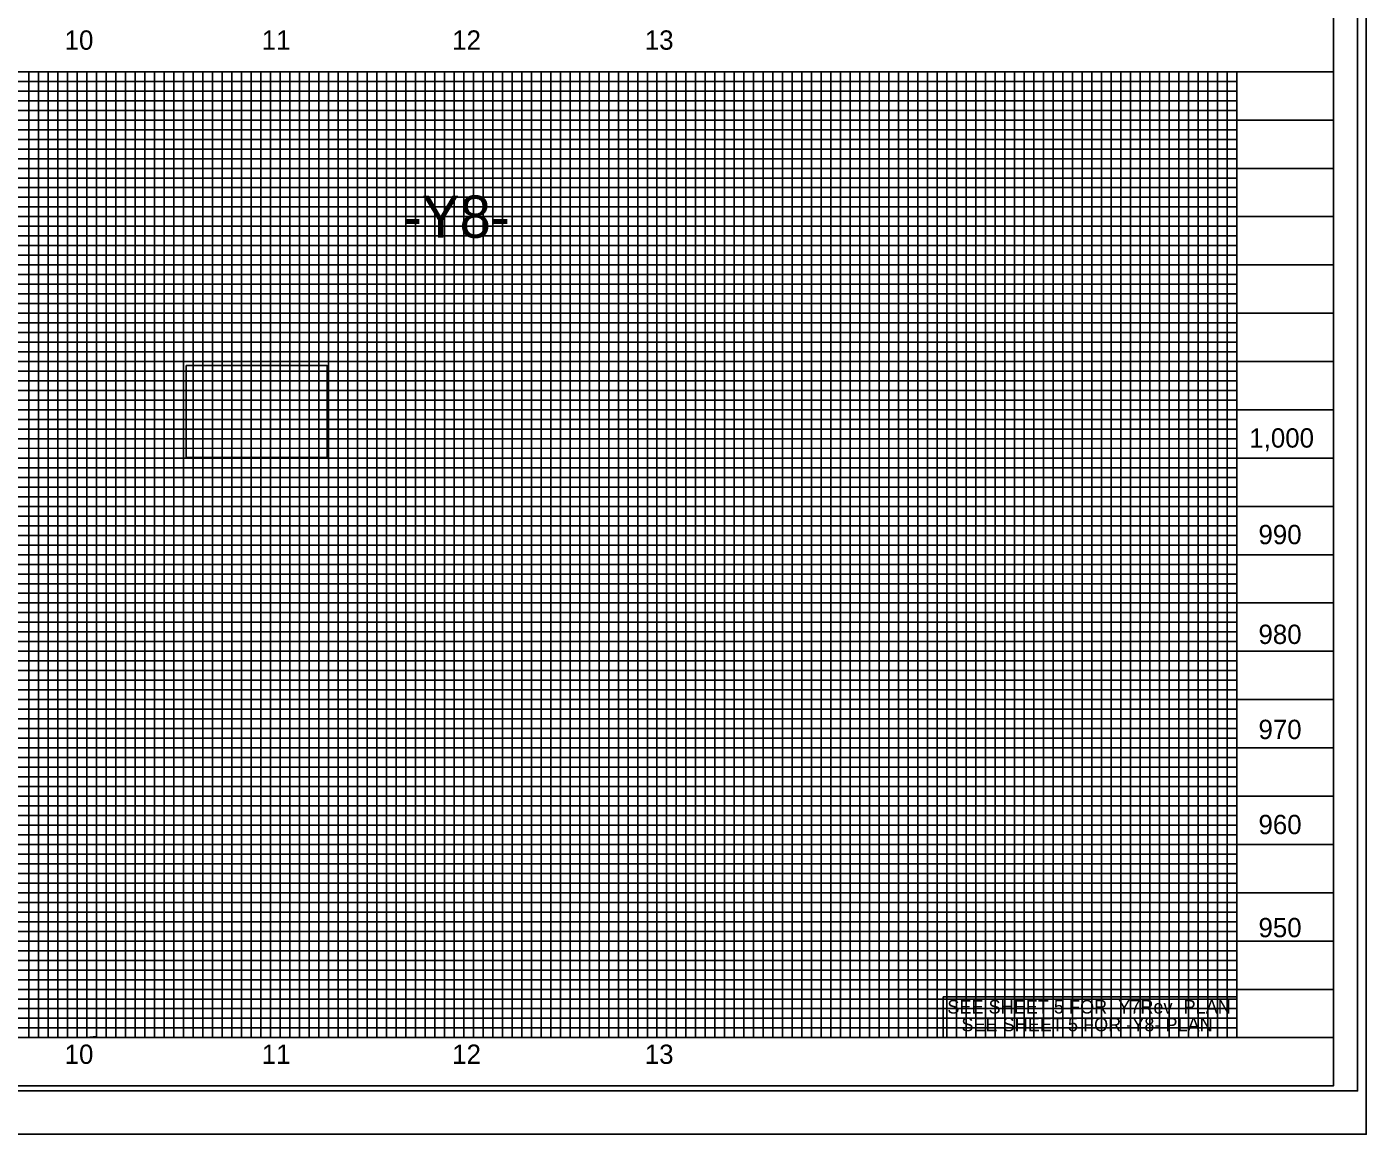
# Model space of a CAD drawing. Extents: x 1621288 to 1629363, y 896995 to 899414.
# Drawn here: x 1628293 to 1628986, y 896995 to 897568 of the extents above; entities that cross this region are included whole.
import ezdxf

# ---------------------------------------------------------------- set-up
doc = ezdxf.new("R2010")
doc.units = 0
for name, color, linetype in [('Exist Profile Cell', 7, 'Continuous'), ('Exist Structure Minor Pipes CMAP 112inx75in', 7, 'Continuous'), ('Exist Vertical Profile Horizontal Axis Label Major', 7, 'Continuous'), ('Exist XS Ground Line', 7, 'Continuous'), ('Prop Horizontal Alignment Curve and Spiral Data', 7, 'Continuous'), ('Prop Terminator CELL', 7, 'Continuous'), ('Prop Vertical Profile Curve Label', 7, 'Continuous'), ('Prop Vertical Profile Grade', 7, 'Continuous'), ('Prop VPI Label', 7, 'Continuous'), ('Sheet Layout Plan Border', 7, 'Continuous'), ('Sheet Layout Profile Border', 7, 'Continuous'), ('Sheet Layout Profile Border Port 2', 7, 'Continuous')]:
    doc.layers.add(name, color=color, linetype=linetype)

msp = doc.modelspace()

# ---------------------------------------------------------------- linework, layer by layer
at = {"layer": 'Exist Profile Cell'}
for p, q in [((1627519.38, 897539.66), (1628919.38, 897539.66)), ((1628919.38, 897534.66), (1627519.38, 897534.66)), ((1627519.38, 897529.66), (1628919.38, 897529.66)), ((1628919.38, 897524.66), (1627519.38, 897524.66)), ((1627519.38, 897514.66), (1628919.38, 897514.66)), ((1628919.38, 897509.66), (1627519.38, 897509.66)), ((1627519.38, 897504.66), (1628919.38, 897504.66)), ((1628919.38, 897499.66), (1627519.38, 897499.66)), ((1627519.38, 897489.66), (1628919.38, 897489.66)), ((1628919.38, 897484.66), (1627519.38, 897484.66)), ((1627519.38, 897479.66), (1628919.38, 897479.66)), ((1628919.38, 897474.66), (1627519.38, 897474.66)), ((1627519.38, 897464.66), (1628919.38, 897464.66)), ((1628919.38, 897459.66), (1627519.38, 897459.66)), ((1627519.38, 897454.66), (1628919.38, 897454.66)), ((1628919.38, 897449.66), (1627519.38, 897449.66)), ((1627519.38, 897439.66), (1628919.38, 897439.66)), ((1628919.38, 897434.66), (1627519.38, 897434.66)), ((1627519.38, 897429.66), (1628919.38, 897429.66)), ((1628919.38, 897424.66), (1627519.38, 897424.66)), ((1627519.38, 897414.66), (1628919.38, 897414.66)), ((1628919.38, 897409.66), (1627519.38, 897409.66)), ((1627519.38, 897404.66), (1628919.38, 897404.66)), ((1628919.38, 897399.66), (1627519.38, 897399.66)), ((1627519.38, 897389.66), (1628919.38, 897389.66)), ((1628919.38, 897384.66), (1627519.38, 897384.66)), ((1627519.38, 897379.66), (1628919.38, 897379.66)), ((1628919.38, 897374.66), (1627519.38, 897374.66)), ((1627519.38, 897364.66), (1628919.38, 897364.66)), ((1628919.38, 897359.66), (1627519.38, 897359.66)), ((1627519.38, 897354.66), (1628919.38, 897354.66)), ((1628919.38, 897349.66), (1627519.38, 897349.81)), ((1627519.38, 897339.66), (1628919.38, 897339.66)), ((1628919.38, 897334.66), (1627519.38, 897334.66)), ((1627519.38, 897329.66), (1628919.38, 897329.66)), ((1628919.38, 897324.66), (1627519.38, 897324.66)), ((1627519.38, 897314.66), (1628919.38, 897314.66)), ((1628919.38, 897309.66), (1627519.38, 897309.66)), ((1627519.38, 897304.66), (1628919.38, 897304.66)), ((1628919.38, 897299.66), (1627519.38, 897299.66)), ((1627519.38, 897289.66), (1628919.38, 897289.66)), ((1628919.38, 897284.66), (1627519.38, 897284.66)), ((1627519.38, 897279.66), (1628919.38, 897279.66)), ((1628919.38, 897274.66), (1627519.38, 897274.66)), ((1627519.38, 897264.66), (1628919.38, 897264.66)), ((1628919.38, 897259.66), (1627519.38, 897259.66)), ((1627519.38, 897254.66), (1628919.38, 897254.66)), ((1628919.38, 897249.66), (1627519.38, 897249.66)), ((1627519.38, 897239.66), (1628919.38, 897239.66)), ((1628919.38, 897234.66), (1627519.38, 897234.66)), ((1627519.38, 897229.66), (1628919.38, 897229.66)), ((1628919.38, 897224.66), (1627519.38, 897224.66)), ((1627519.38, 897214.66), (1628919.38, 897214.66)), ((1628919.38, 897209.66), (1627519.38, 897209.66)), ((1627519.38, 897204.66), (1628919.38, 897204.66)), ((1628919.38, 897199.66), (1627519.38, 897199.66)), ((1627519.38, 897189.66), (1628919.38, 897189.66)), ((1628919.38, 897184.66), (1627519.38, 897184.66)), ((1627519.38, 897179.66), (1628919.38, 897179.66)), ((1628919.38, 897174.66), (1627519.38, 897174.66)), ((1627519.38, 897164.66), (1628919.38, 897164.66)), ((1628919.38, 897159.66), (1627519.38, 897159.66)), ((1627519.38, 897154.66), (1628919.38, 897154.66)), ((1628919.38, 897149.66), (1627519.38, 897149.66)), ((1627519.38, 897139.66), (1628919.38, 897139.66)), ((1628919.38, 897134.66), (1627519.38, 897134.66)), ((1627519.38, 897129.66), (1628919.38, 897129.66)), ((1628919.38, 897124.66), (1627519.38, 897124.66)), ((1627519.38, 897114.66), (1628919.38, 897114.66)), ((1628919.38, 897109.66), (1627519.38, 897109.66)), ((1627519.38, 897104.66), (1628919.38, 897104.66)), ((1628919.38, 897099.66), (1627519.38, 897099.66)), ((1627519.38, 897089.66), (1628919.38, 897089.66)), ((1628919.38, 897084.66), (1627519.38, 897084.66)), ((1627519.38, 897079.66), (1628919.38, 897079.66)), ((1628919.38, 897074.66), (1627519.38, 897074.66)), ((1627519.38, 897064.66), (1628919.38, 897064.66)), ((1628919.38, 897059.66), (1627519.38, 897059.66)), ((1627519.38, 897054.66), (1628919.38, 897054.66)), ((1627519.38, 897049.66), (1628919.38, 897049.66)), ((1628919.38, 897049.66), (1628919.38, 897049.66))]:
    msp.add_line(p, q, dxfattribs=at)
for points in [[(1628289.38, 897544.66), (1628299.38, 897544.66), (1628299.38, 897044.66), (1628304.38, 897044.66), (1628304.38, 897544.66), (1628309.38, 897544.66), (1628309.38, 897044.66), (1628314.38, 897044.66), (1628314.38, 897544.66), (1628324.38, 897544.66), (1628324.38, 897044.66), (1628329.08, 897045.21), (1628329.38, 897044.66), (1628329.38, 897544.66), (1628334.38, 897544.66), (1628334.38, 897044.66), (1628339.38, 897044.66), (1628339.38, 897544.66), (1628349.38, 897544.66), (1628349.38, 897044.66), (1628354.38, 897044.66)], [(1628354.38, 897044.66), (1628354.38, 897544.66), (1628359.38, 897544.66), (1628359.38, 897044.66), (1628364.38, 897044.66), (1628364.38, 897544.66), (1628374.38, 897544.66), (1628374.38, 897044.66), (1628379.38, 897044.66), (1628379.38, 897544.66), (1628384.38, 897544.66), (1628384.38, 897044.66), (1628389.38, 897044.66), (1628389.38, 897544.66), (1628399.38, 897544.66), (1628399.38, 897044.66), (1628404.38, 897044.66), (1628404.38, 897544.66), (1628409.38, 897544.66), (1628409.38, 897044.66), (1628414.38, 897044.66), (1628414.38, 897544.66), (1628424.38, 897544.66), (1628424.38, 897044.66), (1628429.38, 897044.66), (1628429.38, 897544.66), (1628434.38, 897544.66), (1628434.38, 897044.66), (1628439.38, 897044.66), (1628439.38, 897544.66), (1628449.38, 897544.66), (1628449.38, 897044.66), (1628454.38, 897044.66), (1628454.38, 897544.66), (1628459.38, 897544.66), (1628459.38, 897044.66), (1628464.38, 897044.66), (1628464.38, 897544.66), (1628474.38, 897544.66), (1628474.38, 897044.66), (1628479.38, 897044.66), (1628479.38, 897544.66), (1628484.38, 897544.66), (1628484.38, 897044.66), (1628489.38, 897044.66), (1628489.38, 897544.66), (1628499.38, 897544.66), (1628499.38, 897044.66), (1628504.38, 897044.66), (1628504.38, 897544.66), (1628509.38, 897544.66), (1628509.38, 897044.66), (1628514.38, 897044.66), (1628514.38, 897544.66), (1628524.38, 897544.66), (1628524.38, 897044.66), (1628529.38, 897044.66), (1628529.38, 897544.66), (1628534.38, 897544.66), (1628534.38, 897044.66), (1628539.38, 897044.66), (1628539.38, 897544.66), (1628549.38, 897544.66), (1628549.38, 897044.66), (1628554.38, 897044.66), (1628554.38, 897544.66), (1628559.38, 897544.66), (1628559.38, 897044.66), (1628564.38, 897044.66), (1628564.38, 897544.66), (1628574.38, 897544.66), (1628574.38, 897044.66), (1628579.38, 897044.66), (1628579.38, 897544.66), (1628584.38, 897544.66), (1628584.38, 897044.66), (1628589.38, 897044.66), (1628589.38, 897544.66), (1628599.38, 897544.66), (1628599.38, 897044.66), (1628604.38, 897044.66), (1628604.38, 897544.66), (1628609.38, 897544.66), (1628609.38, 897044.66), (1628614.38, 897044.66), (1628614.38, 897544.66), (1628624.38, 897544.66), (1628624.38, 897044.66), (1628629.38, 897044.66), (1628629.38, 897544.66), (1628634.38, 897544.66), (1628634.38, 897044.66), (1628639.38, 897044.66), (1628639.38, 897544.66), (1628649.38, 897544.66), (1628649.38, 897044.66), (1628654.38, 897044.66), (1628654.38, 897544.66), (1628659.38, 897544.66), (1628659.38, 897044.66)], [(1628659.38, 897044.66), (1628664.38, 897044.66), (1628664.38, 897544.66), (1628674.38, 897544.66), (1628674.38, 897044.66), (1628679.38, 897044.66), (1628679.38, 897544.66), (1628684.38, 897544.66), (1628684.38, 897044.66), (1628689.38, 897044.66), (1628689.38, 897544.66), (1628699.38, 897544.66), (1628699.38, 897044.66), (1628704.38, 897044.66), (1628704.38, 897544.66), (1628709.38, 897544.66), (1628709.38, 897044.66), (1628714.38, 897044.66), (1628714.38, 897544.66), (1628724.38, 897544.66), (1628724.38, 897044.66), (1628729.38, 897044.66), (1628729.38, 897544.66), (1628734.38, 897544.66), (1628734.38, 897044.66), (1628739.38, 897044.66), (1628739.38, 897544.66), (1628749.38, 897544.66), (1628749.38, 897044.66), (1628754.38, 897044.66), (1628754.38, 897544.66), (1628759.38, 897544.66), (1628759.38, 897044.66), (1628764.38, 897044.66), (1628764.38, 897544.66), (1628774.38, 897544.66), (1628774.38, 897044.66), (1628779.38, 897044.66), (1628779.38, 897544.66), (1628784.38, 897544.66), (1628784.38, 897044.66), (1628789.38, 897044.66), (1628789.38, 897544.66), (1628799.38, 897544.66), (1628799.38, 897044.66), (1628804.38, 897044.66), (1628804.38, 897544.66), (1628809.38, 897544.66), (1628809.38, 897044.66), (1628814.38, 897044.66), (1628814.38, 897544.66), (1628824.38, 897544.66), (1628824.38, 897044.66), (1628829.38, 897044.66), (1628829.38, 897544.66), (1628834.38, 897544.66), (1628834.38, 897044.66), (1628839.38, 897044.66), (1628839.38, 897544.66), (1628849.38, 897544.66), (1628849.38, 897044.66), (1628854.38, 897044.66), (1628854.38, 897544.66), (1628859.38, 897544.66), (1628859.38, 897044.66), (1628864.38, 897044.66), (1628864.38, 897544.66), (1628874.38, 897544.66), (1628874.38, 897044.66), (1628879.38, 897044.66), (1628879.38, 897544.66), (1628884.38, 897544.66), (1628884.38, 897044.66), (1628889.38, 897044.66), (1628889.38, 897544.66), (1628899.38, 897544.66), (1628899.38, 897044.66), (1628904.38, 897044.66), (1628904.38, 897544.66), (1628909.38, 897544.66), (1628909.38, 897044.66), (1628914.38, 897044.66), (1628914.38, 897544.66), (1628919.38, 897544.66)]]:
    msp.add_lwpolyline(points, dxfattribs=at)
at = {"layer": 'Exist Structure Minor Pipes CMAP 112inx75in'}
msp.add_lwpolyline([(1628319.38, 897494.66), (1628719.38, 897494.66), (1628719.38, 897094.66), (1628319.38, 897094.66)], close=True, dxfattribs=at)
at = {"layer": 'Exist Vertical Profile Horizontal Axis Label Major'}
for points in [[(1628484.38, 897484.66), (1628554.38, 897484.66), (1628554.38, 897454.66), (1628484.38, 897454.66)], [(1628375.76, 897392.57), (1628448.75, 897392.57), (1628448.75, 897345.04), (1628375.76, 897345.04)], [(1628767.46, 897065.86), (1628919.38, 897065.86), (1628919.38, 897044.66), (1628767.46, 897044.66)]]:
    msp.add_lwpolyline(points, close=True, dxfattribs=at)
at = {"layer": 'Exist XS Ground Line'}
for p, q in [((1627469.38, 897544.66), (1628969.38, 897544.66)), ((1628969.38, 897044.66), (1627469.38, 897044.66)), ((1627469.38, 897019.66), (1628969.38, 897019.66))]:
    msp.add_line(p, q, dxfattribs=at)
msp.add_lwpolyline([(1628969.38, 898069.66), (1627469.38, 898069.66), (1627469.38, 897019.66), (1628969.38, 897019.66)], close=True, dxfattribs=at)
at = {"layer": 'Prop Terminator CELL'}
msp.add_lwpolyline([(1627519.38, 897544.66), (1628919.38, 897544.66), (1628919.38, 897044.66), (1627519.38, 897044.66)], close=True, dxfattribs=at)
at = {"layer": 'Prop Vertical Profile Curve Label'}
msp.add_lwpolyline([(1627315.38, 897017.11), (1628981.88, 897017.11), (1628981.88, 898072.21), (1627315.38, 898072.21)], close=True, dxfattribs=at)
at = {"layer": 'Prop Vertical Profile Grade'}
for points in [[(1628244.38, 897044.66), (1628294.38, 897044.66), (1628294.38, 897544.66), (1628344.38, 897544.66), (1628344.38, 897044.66), (1628394.38, 897044.66), (1628394.38, 897544.66), (1628444.38, 897544.66), (1628444.38, 897044.66), (1628494.38, 897044.66), (1628494.38, 897544.66), (1628544.38, 897544.66), (1628544.38, 897044.66), (1628594.38, 897044.66), (1628594.38, 897544.66), (1628644.38, 897544.66), (1628644.38, 897044.66), (1628694.38, 897044.66), (1628694.38, 897544.66), (1628744.38, 897544.66), (1628744.38, 897044.66), (1628794.38, 897044.66), (1628794.38, 897544.66), (1628844.38, 897544.66), (1628844.38, 897044.66), (1628894.38, 897044.66), (1628894.38, 897544.66)], [(1627469.38, 897519.66), (1628969.38, 897519.66)], [(1628969.38, 897469.66), (1627469.38, 897469.66), (1627469.38, 897419.66), (1628969.38, 897419.66)], [(1628969.38, 897369.66), (1627469.38, 897369.66), (1627469.38, 897319.66), (1628969.38, 897319.66)], [(1628969.38, 897269.66), (1627469.38, 897269.66), (1627469.38, 897219.66), (1628969.38, 897219.66)], [(1628969.38, 897169.66), (1627469.38, 897169.66), (1627469.38, 897119.66), (1628969.38, 897119.66)], [(1628969.38, 897069.66), (1627469.38, 897069.66)]]:
    msp.add_lwpolyline(points, dxfattribs=at)
at = {"layer": 'Prop VPI Label'}
for p, q in [((1628269.38, 897544.66), (1628319.38, 897544.66)), ((1628369.38, 897544.66), (1628419.38, 897544.66)), ((1628469.38, 897544.66), (1628519.38, 897544.66)), ((1628569.38, 897544.66), (1628619.38, 897544.66)), ((1628669.38, 897544.66), (1628719.38, 897544.66)), ((1628769.38, 897544.66), (1628819.38, 897544.66)), ((1628869.38, 897544.66), (1628919.38, 897544.66)), ((1628869.38, 897044.66), (1628869.38, 897044.66))]:
    msp.add_line(p, q, dxfattribs=at)
for points in [[(1628269.38, 897544.66), (1628319.38, 897544.66), (1628319.38, 897044.66), (1628369.38, 897044.66), (1628369.38, 897544.66), (1628419.38, 897544.66), (1628419.38, 897044.66), (1628469.38, 897044.66), (1628469.38, 897544.66), (1628519.38, 897544.66), (1628519.38, 897044.66), (1628569.38, 897044.66), (1628569.38, 897544.66), (1628619.38, 897544.66), (1628619.38, 897044.66), (1628669.38, 897044.66), (1628669.38, 897544.66), (1628719.38, 897544.66), (1628719.38, 897044.66), (1628769.38, 897044.66), (1628769.38, 897544.66), (1628819.38, 897544.66), (1628819.38, 897044.66), (1628869.38, 897044.66), (1628869.38, 897044.66), (1628869.38, 897544.66), (1628919.38, 897544.66), (1628919.38, 897044.66)], [(1628969.38, 897494.66), (1627469.38, 897494.66)], [(1628969.38, 897444.66), (1627469.38, 897444.66), (1627469.38, 897394.66), (1628969.38, 897394.66)], [(1628969.38, 897344.66), (1627469.38, 897344.66), (1627469.38, 897294.66), (1628969.38, 897294.66)], [(1628969.38, 897244.66), (1627469.38, 897244.66), (1627469.38, 897194.66), (1628969.38, 897194.66)], [(1628969.38, 897144.66), (1627469.38, 897144.66), (1627469.38, 897144.66), (1627469.38, 897094.66), (1628969.38, 897094.66)], [(1628969.38, 897044.66), (1627469.38, 897044.66)]]:
    msp.add_lwpolyline(points, dxfattribs=at)
at = {"layer": 'Sheet Layout Plan Border'}
msp.add_lwpolyline([(1627302.38, 896994.66), (1628986.38, 896994.66), (1628986.38, 898094.66), (1627302.38, 898094.66)], close=True, dxfattribs=at)
at = {"layer": 'Sheet Layout Profile Border'}
msp.add_line((1627302.38, 896994.66), (1628986.38, 896994.66), dxfattribs=at)
at = {"layer": 'Sheet Layout Profile Border Port 2'}
for p, q in [((1627469.38, 897544.66), (1628969.27, 897544.66)), ((1628319.38, 897544.66), (1628319.38, 897044.66)), ((1628369.38, 897544.66), (1628369.38, 897044.66)), ((1628419.38, 897544.66), (1628419.38, 897044.66)), ((1628469.38, 897544.66), (1628469.38, 897044.66)), ((1628519.38, 897544.66), (1628519.38, 897044.66)), ((1628569.38, 897544.66), (1628569.38, 897044.66)), ((1628619.38, 897544.66), (1628619.38, 897044.66)), ((1628669.38, 897544.66), (1628669.38, 897044.66)), ((1628719.38, 897544.66), (1628719.38, 897044.66)), ((1628769.38, 897544.66), (1628769.38, 897044.66)), ((1628819.38, 897544.66), (1628819.38, 897044.66)), ((1628869.38, 897544.66), (1628869.38, 897044.66)), ((1628919.38, 897544.66), (1628919.38, 897044.66)), ((1627469.38, 897494.66), (1628969.27, 897494.66)), ((1627469.38, 897444.66), (1628969.27, 897444.66)), ((1627469.38, 897394.66), (1628969.27, 897394.66)), ((1627469.38, 897344.66), (1628969.27, 897344.66)), ((1627469.38, 897294.66), (1628969.27, 897294.66)), ((1627469.38, 897244.66), (1628969.27, 897244.66)), ((1627469.38, 897194.66), (1628969.27, 897194.66)), ((1627469.38, 897144.66), (1628969.27, 897144.66)), ((1627469.38, 897094.66), (1628969.27, 897094.66))]:
    msp.add_line(p, q, dxfattribs=at)

# ---------------------------------------------------------------- texts
at = {"layer": 'Exist Vertical Profile Horizontal Axis Label Major'}
for s, p in [('SEE SHEET 5 FOR -Y7Rev- PLAN', (1628769.62, 897057.14)), ('SEE SHEET 5 FOR -Y8- PLAN', (1628776.89, 897047.96))]:
    msp.add_text(s, height=7, dxfattribs=at).set_placement(p)
at = {"layer": 'Prop Horizontal Alignment Curve and Spiral Data'}
for s, height, p in [('10', 10, (1628312.86, 897556.07)), ('11', 10, (1628414.83, 897556.07)), ('12', 10, (1628513.4, 897556.07)), ('13', 10, (1628613.07, 897556.07)), ('-Y8-', 21.875, (1628487.93, 897458.72)), ('1,000', 10, (1628925.89, 897350.09)), ('990', 10, (1628930.63, 897300.09)), ('980', 10, (1628930.63, 897248.44)), ('970', 10, (1628930.63, 897199.22)), ('960', 10, (1628930.63, 897149.99)), ('950', 10, (1628930.63, 897096.63)), ('10', 10, (1628312.86, 897031.07)), ('11', 10, (1628414.83, 897031.07)), ('12', 10, (1628513.4, 897031.07))]:
    msp.add_text(s, height=height, dxfattribs=at).set_placement(p)
at = {"layer": 'Prop VPI Label'}
msp.add_text('13', height=10, dxfattribs=at).set_placement((1628613.07, 897031.07))

doc.saveas('drawing.dxf')
